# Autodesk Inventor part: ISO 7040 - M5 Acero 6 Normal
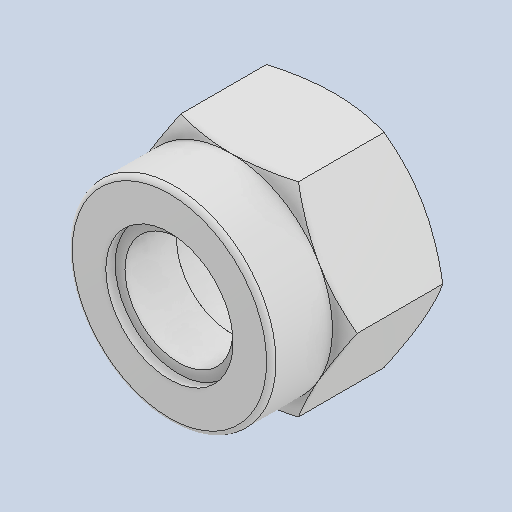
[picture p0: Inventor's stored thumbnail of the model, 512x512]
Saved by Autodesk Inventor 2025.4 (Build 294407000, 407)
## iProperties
Created: 2026-09
Part Number: ISO 7040 - M5 Acero 6 Normal
Material: Generic
Description: Tuerca autoblocante hexagonal normal ISO 7040 - M5
Document SubType Name: Modeling
Designer: AdminForWorker
Density: 1 g/cm^3
Appearance: Default
Title: Tuerca autoblocante hexagonal normal ISO 7040 - M5 Acero 6 Normal v1
Author: AdminForWorker
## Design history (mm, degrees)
feature "Body5"
feature "Body6"
body "Solid1"
body "Solid2"
